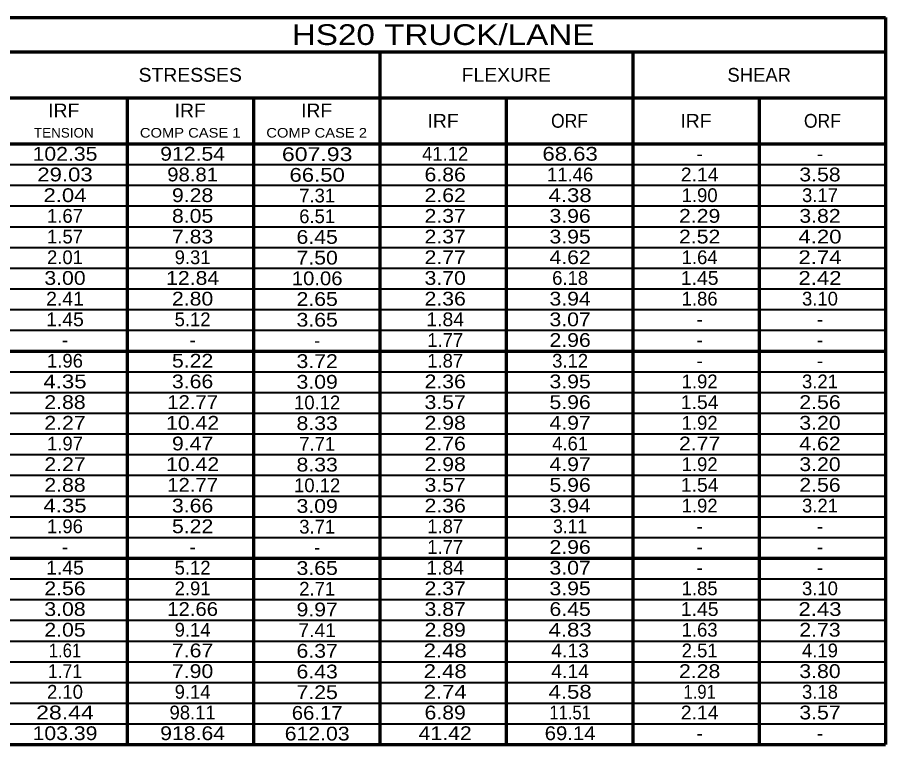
# Model space of a CAD drawing. Extents: x -1807 to -1668, y -81 to 6.
# Drawn here: x -1713.57 to -1675.8, y -25.85 to 5.78 of the extents above; entities that cross this region are included whole.
import ezdxf
from ezdxf.enums import TextEntityAlignment as Align

# ---------------------------------------------------------------- set-up
doc = ezdxf.new("R2010")
doc.units = 0
doc.header["$LTSCALE"] = 0.24
doc.layers.add('1', color=7, linetype='Continuous', lineweight=70)
doc.layers.add('5', color=7, linetype='Continuous', lineweight=40)
doc.layers.add('21', color=7, linetype='Continuous')
doc.layers.add('9', color=7, linetype='Continuous')

msp = doc.modelspace()

# ---------------------------------------------------------------- linework, layer by layer
at = {"layer": '1'}
for p, q in [((-1761.797, 5.7798), (-1675.797, 5.7798)), ((-1675.797, 5.7798), (-1675.797, -25.8503)), ((-1761.797, 4.2798), (-1675.797, 4.2798)), ((-1697.797, 4.2798), (-1697.797, -25.8503)), ((-1686.797, 4.2798), (-1686.797, -25.8503)), ((-1752.797, 2.2798), (-1675.797, 2.2798)), ((-1708.797, 2.2798), (-1708.797, -25.8503)), ((-1703.297, 2.2798), (-1703.297, -25.8503)), ((-1692.297, 2.2798), (-1692.297, -25.8503)), ((-1681.297, 2.2798), (-1681.297, -25.8503)), ((-1761.797, 0.2798), (-1675.797, 0.2798)), ((-1761.797, -8.7306), (-1675.797, -8.7306)), ((-1761.797, -17.741), (-1675.797, -17.741)), ((-1761.797, -25.8503), (-1675.797, -25.8503))]:
    msp.add_line(p, q, dxfattribs=at)
at = {"layer": '5'}
for p, q in [((-1757.797, -0.6212), (-1675.797, -0.6212)), ((-1757.797, -1.5222), (-1675.797, -1.5222)), ((-1757.797, -2.4232), (-1675.797, -2.4232)), ((-1757.797, -3.3243), (-1675.797, -3.3243)), ((-1757.797, -4.2253), (-1675.797, -4.2253)), ((-1757.797, -5.1264), (-1675.797, -5.1264)), ((-1757.797, -6.0274), (-1675.797, -6.0274)), ((-1757.797, -6.9285), (-1675.797, -6.9285)), ((-1757.797, -7.8295), (-1675.797, -7.8295)), ((-1757.797, -9.6316), (-1675.797, -9.6316)), ((-1757.797, -10.5327), (-1675.797, -10.5327)), ((-1757.797, -11.4337), (-1675.797, -11.4337)), ((-1757.797, -12.3347), (-1675.797, -12.3347)), ((-1757.797, -13.2357), (-1675.797, -13.2357)), ((-1757.797, -14.1368), (-1675.797, -14.1368)), ((-1757.797, -15.0378), (-1675.797, -15.0378)), ((-1757.797, -15.9389), (-1675.797, -15.9389)), ((-1757.797, -16.8399), (-1675.797, -16.8399)), ((-1757.797, -18.642), (-1675.797, -18.642)), ((-1757.797, -19.5431), (-1675.797, -19.5431)), ((-1757.797, -20.4441), (-1675.797, -20.4441)), ((-1757.797, -21.3452), (-1675.797, -21.3452)), ((-1757.797, -22.2462), (-1675.797, -22.2462)), ((-1757.797, -23.1472), (-1675.797, -23.1472)), ((-1757.797, -24.0482), (-1675.797, -24.0482)), ((-1757.797, -24.9493), (-1675.797, -24.9493))]:
    msp.add_line(p, q, dxfattribs=at)

# ---------------------------------------------------------------- texts
at = {"layer": '21'}
for s, height, width, p in [('STRESSES', 0.6, 1.05, (-1706.0468, 2.9798)), ('FLEXURE', 0.6, 1.05, (-1692.2968, 2.9798)), ('IRF', 0.6, 1.05, (-1711.5468, 1.4298)), ('IRF', 0.6, 1.05, (-1706.0468, 1.4298)), ('IRF', 0.6, 1.05, (-1700.5468, 1.4298)), ('IRF', 0.6, 1.05, (-1695.0468, 0.9798)), ('ORF', 0.6, 0.95, (-1689.5469, 0.9798)), ('IRF', 0.6, 1.05, (-1684.0468, 0.9798)), ('ORF', 0.6, 0.95, (-1678.5469, 0.9798)), ('TENSION', 0.4167, 1.05, (-1711.5468, 0.5525)), ('COMP CASE 1', 0.4167, 1.15, (-1706.0469, 0.5525)), ('COMP CASE 2', 0.4167, 1.15, (-1700.5469, 0.5525))]:
    msp.add_text(s, height=height, dxfattribs=dict(at, width=width)).set_placement(p, align=Align.CENTER)
msp.add_text('SHEAR', height=0.6, dxfattribs=at).set_placement((-1681.2968, 2.9798), align=Align.CENTER)
at = {"layer": '9'}
for s, height, width, p in [('HS20 TRUCK/LANE', 0.9, 1.2, (-1695.0465, 4.5798)), ('102.35', 0.6, 1.15, (-1711.4943, -0.4538)), ('912.54', 0.6, 1.15, (-1705.9427, -0.4538)), ('607.93', 0.6, 1.25, (-1700.5249, -0.4705)), ('68.63', 0.6, 1.2, (-1689.522, -0.4538)), ('29.03', 0.6, 1.2, (-1711.4944, -1.3538)), ('98.81', 0.6, 1.1, (-1705.9428, -1.3538)), ('6.86', 0.6, 1.15, (-1694.9565, -1.3538)), ('2.14', 0.6, 1.05, (-1683.8867, -1.3538)), ('3.58', 0.6, 1.15, (-1678.6528, -1.3538)), ('66.50', 0.6, 1.2, (-1700.5249, -1.3705)), ('2.04', 0.6, 1.2, (-1711.4944, -2.2538)), ('9.28', 0.6, 1.15, (-1705.9428, -2.2538)), ('2.62', 0.6, 1.15, (-1694.9565, -2.2538)), ('4.38', 0.6, 1.2, (-1689.522, -2.2538)), ('8.05', 0.6, 1.15, (-1705.9428, -3.1538)), ('2.37', 0.6, 1.15, (-1694.9565, -3.1538)), ('3.96', 0.6, 1.15, (-1689.522, -3.1538)), ('2.29', 0.6, 1.15, (-1683.8867, -3.1538)), ('3.82', 0.6, 1.15, (-1678.6528, -3.1538)), ('7.83', 0.6, 1.15, (-1705.9428, -4.0538)), ('6.45', 0.6, 1.15, (-1700.5249, -4.0705)), ('2.37', 0.6, 1.15, (-1694.9565, -4.0538)), ('3.95', 0.6, 1.15, (-1689.522, -4.0538)), ('2.52', 0.6, 1.15, (-1683.8867, -4.0538)), ('4.20', 0.6, 1.2, (-1678.6528, -4.0538)), ('7.50', 0.6, 1.15, (-1700.5249, -4.9705)), ('2.77', 0.6, 1.15, (-1694.9565, -4.9538)), ('4.62', 0.6, 1.15, (-1689.5219, -4.9538)), ('2.74', 0.6, 1.2, (-1678.6528, -4.9538)), ('3.00', 0.6, 1.15, (-1711.4943, -5.8538)), ('12.84', 0.6, 1.15, (-1705.9428, -5.8538)), ('10.06', 0.6, 1.1, (-1700.5249, -5.8705)), ('3.70', 0.6, 1.15, (-1694.9565, -5.8538)), ('1.45', 0.6, 1.05, (-1683.8867, -5.8538)), ('2.42', 0.6, 1.2, (-1678.6528, -5.8538)), ('2.41', 0.6, 1.05, (-1711.4944, -6.7538)), ('2.80', 0.6, 1.15, (-1705.9428, -6.7538)), ('2.65', 0.6, 1.15, (-1700.5249, -6.7705)), ('2.36', 0.6, 1.15, (-1694.9566, -6.7538)), ('3.94', 0.6, 1.15, (-1689.5219, -6.7538)), ('1.45', 0.6, 1.05, (-1711.4944, -7.6538)), ('3.65', 0.6, 1.15, (-1700.5249, -7.6705)), ('1.84', 0.6, 1.05, (-1694.9565, -7.6538)), ('3.07', 0.6, 1.15, (-1689.5219, -7.6538)), ('2.96', 0.6, 1.15, (-1689.522, -8.5538)), ('5.22', 0.6, 1.15, (-1705.9428, -9.4538)), ('3.72', 0.6, 1.15, (-1700.5249, -9.4705)), ('4.35', 0.6, 1.2, (-1711.4944, -10.3538)), ('3.66', 0.6, 1.15, (-1705.9428, -10.3538)), ('3.09', 0.6, 1.15, (-1700.5249, -10.3705)), ('2.36', 0.6, 1.15, (-1694.9566, -10.3538)), ('3.95', 0.6, 1.15, (-1689.522, -10.3538)), ('2.88', 0.6, 1.15, (-1711.4944, -11.2538)), ('12.77', 0.6, 1.1, (-1705.9428, -11.2538)), ('3.57', 0.6, 1.15, (-1694.9565, -11.2538)), ('5.96', 0.6, 1.15, (-1689.522, -11.2538)), ('1.54', 0.6, 1.05, (-1683.8867, -11.2538)), ('2.56', 0.6, 1.15, (-1678.6528, -11.2538)), ('2.27', 0.6, 1.15, (-1711.4944, -12.1538)), ('10.42', 0.6, 1.15, (-1705.9428, -12.1538)), ('8.33', 0.6, 1.15, (-1700.5249, -12.1705)), ('2.98', 0.6, 1.15, (-1694.9565, -12.1538)), ('4.97', 0.6, 1.15, (-1689.5219, -12.1538)), ('3.20', 0.6, 1.15, (-1678.6528, -12.1538)), ('9.47', 0.6, 1.15, (-1705.9428, -13.0538)), ('2.76', 0.6, 1.15, (-1694.9565, -13.0538)), ('2.77', 0.6, 1.15, (-1683.8867, -13.0538)), ('4.62', 0.6, 1.15, (-1678.6528, -13.0538)), ('2.27', 0.6, 1.15, (-1711.4944, -13.9538)), ('10.42', 0.6, 1.15, (-1705.9428, -13.9538)), ('8.33', 0.6, 1.15, (-1700.5249, -13.9705)), ('2.98', 0.6, 1.15, (-1694.9565, -13.9538)), ('4.97', 0.6, 1.15, (-1689.5219, -13.9538)), ('3.20', 0.6, 1.15, (-1678.6528, -13.9538)), ('2.88', 0.6, 1.15, (-1711.4944, -14.8538)), ('12.77', 0.6, 1.1, (-1705.9428, -14.8538)), ('3.57', 0.6, 1.15, (-1694.9565, -14.8538)), ('5.96', 0.6, 1.15, (-1689.522, -14.8538)), ('1.54', 0.6, 1.05, (-1683.8867, -14.8538)), ('2.56', 0.6, 1.15, (-1678.6528, -14.8538)), ('4.35', 0.6, 1.2, (-1711.4944, -15.7538)), ('3.66', 0.6, 1.15, (-1705.9428, -15.7538)), ('3.09', 0.6, 1.15, (-1700.5249, -15.7705)), ('2.36', 0.6, 1.15, (-1694.9566, -15.7538)), ('3.94', 0.6, 1.15, (-1689.5219, -15.7538)), ('5.22', 0.6, 1.15, (-1705.9428, -16.6538)), ('3.11', 0.6, 0.95, (-1689.522, -16.6538)), ('2.96', 0.6, 1.15, (-1689.522, -17.5538)), ('1.45', 0.6, 1.05, (-1711.4944, -18.4538)), ('3.65', 0.6, 1.15, (-1700.5249, -18.4705)), ('1.84', 0.6, 1.05, (-1694.9565, -18.4538)), ('3.07', 0.6, 1.15, (-1689.5219, -18.4538)), ('2.56', 0.6, 1.15, (-1711.4944, -19.3538)), ('2.37', 0.6, 1.15, (-1694.9565, -19.3538)), ('3.95', 0.6, 1.15, (-1689.522, -19.3538)), ('3.08', 0.6, 1.15, (-1711.4944, -20.2538)), ('12.66', 0.6, 1.1, (-1705.9428, -20.2538)), ('9.97', 0.6, 1.15, (-1700.5249, -20.2705)), ('3.87', 0.6, 1.15, (-1694.9565, -20.2538)), ('6.45', 0.6, 1.15, (-1689.5219, -20.2538)), ('1.45', 0.6, 1.05, (-1683.8867, -20.2538)), ('2.43', 0.6, 1.2, (-1678.6528, -20.2538)), ('2.05', 0.6, 1.15, (-1711.4944, -21.1538)), ('7.41', 0.6, 1.05, (-1700.5249, -21.1705)), ('2.89', 0.6, 1.15, (-1694.9566, -21.1538)), ('4.83', 0.6, 1.2, (-1689.522, -21.1538)), ('2.73', 0.6, 1.15, (-1678.6528, -21.1538)), ('1.61', 0.6, 0.9, (-1711.4944, -22.0538)), ('7.67', 0.6, 1.15, (-1705.9428, -22.0538)), ('6.37', 0.6, 1.15, (-1700.5249, -22.0705)), ('2.48', 0.6, 1.2, (-1694.9565, -22.0538)), ('4.13', 0.6, 1.05, (-1689.522, -22.0538)), ('1.71', 0.6, 0.95, (-1711.4943, -22.9538)), ('7.90', 0.6, 1.15, (-1705.9428, -22.9538)), ('6.43', 0.6, 1.15, (-1700.5249, -22.9705)), ('2.48', 0.6, 1.2, (-1694.9565, -22.9538)), ('4.14', 0.6, 1.05, (-1689.522, -22.9538)), ('2.28', 0.6, 1.15, (-1683.8867, -22.9538)), ('3.80', 0.6, 1.15, (-1678.6528, -22.9538)), ('7.25', 0.6, 1.15, (-1700.5249, -23.8705)), ('2.74', 0.6, 1.2, (-1694.9565, -23.8538)), ('4.58', 0.6, 1.2, (-1689.522, -23.8538)), ('1.91', 0.6, 0.9, (-1683.8867, -23.8538)), ('28.44', 0.6, 1.25, (-1711.4944, -24.7538)), ('66.17', 0.6, 1.1, (-1700.5249, -24.7705)), ('6.89', 0.6, 1.15, (-1694.9565, -24.7538)), ('11.51', 0.6, 0.9, (-1689.5219, -24.7538)), ('2.14', 0.6, 1.05, (-1683.8867, -24.7538)), ('3.57', 0.6, 1.15, (-1678.6528, -24.7538)), ('103.39', 0.6, 1.15, (-1711.4943, -25.6538)), ('918.64', 0.6, 1.15, (-1705.9428, -25.6538)), ('612.03', 0.6, 1.15, (-1700.5249, -25.6705)), ('41.42', 0.6, 1.15, (-1694.9565, -25.6538)), ('69.14', 0.6, 1.1, (-1689.522, -25.6538))]:
    msp.add_text(s, height=height, dxfattribs=dict(at, width=width)).set_placement(p, align=Align.CENTER)
for s, p in [('41.12', (-1694.9565, -0.4538)), ('-', (-1683.8867, -0.4538)), ('-', (-1678.6528, -0.4538)), ('11.46', (-1689.522, -1.3538)), ('7.31', (-1700.5249, -2.2705)), ('1.90', (-1683.8867, -2.2538)), ('3.17', (-1678.6528, -2.2538)), ('1.67', (-1711.4943, -3.1538)), ('6.51', (-1700.5248, -3.1705)), ('1.57', (-1711.4944, -4.0538)), ('2.01', (-1711.4943, -4.9538)), ('9.31', (-1705.9428, -4.9538)), ('1.64', (-1683.8867, -4.9538)), ('6.18', (-1689.5219, -5.8538)), ('1.86', (-1683.8867, -6.7538)), ('3.10', (-1678.6527, -6.7538)), ('5.12', (-1705.9428, -7.6538)), ('-', (-1683.8867, -7.6538)), ('-', (-1678.6528, -7.6538)), ('-', (-1711.4944, -8.5538)), ('-', (-1705.9428, -8.5538)), ('-', (-1700.5249, -8.5705)), ('1.77', (-1694.9565, -8.5538)), ('-', (-1683.8867, -8.5538)), ('-', (-1678.6528, -8.5538)), ('1.96', (-1711.4943, -9.4538)), ('1.87', (-1694.9565, -9.4538)), ('3.12', (-1689.522, -9.4538)), ('-', (-1683.8867, -9.4538)), ('-', (-1678.6528, -9.4538)), ('1.92', (-1683.8867, -10.3538)), ('3.21', (-1678.6528, -10.3538)), ('10.12', (-1700.5249, -11.2705)), ('1.92', (-1683.8867, -12.1538)), ('1.97', (-1711.4943, -13.0538)), ('4.61', (-1689.5219, -13.0538)), ('7.71', (-1700.5249, -13.0705)), ('1.92', (-1683.8867, -13.9538)), ('10.12', (-1700.5249, -14.8705)), ('1.92', (-1683.8867, -15.7538)), ('3.21', (-1678.6528, -15.7538)), ('1.96', (-1711.4943, -16.6538)), ('3.71', (-1700.5249, -16.6705)), ('1.87', (-1694.9565, -16.6538)), ('-', (-1683.8867, -16.6538)), ('-', (-1678.6528, -16.6538)), ('1.77', (-1694.9565, -17.5538)), ('-', (-1711.4944, -17.5538)), ('-', (-1705.9428, -17.5538)), ('-', (-1700.5249, -17.5705)), ('-', (-1683.8867, -17.5538)), ('-', (-1678.6528, -17.5538)), ('5.12', (-1705.9428, -18.4538)), ('-', (-1683.8867, -18.4538)), ('-', (-1678.6528, -18.4538)), ('2.91', (-1705.9428, -19.3538)), ('2.71', (-1700.5249, -19.3705)), ('1.85', (-1683.8867, -19.3538)), ('3.10', (-1678.6527, -19.3538)), ('9.14', (-1705.9427, -21.1538)), ('1.63', (-1683.8867, -21.1538)), ('2.51', (-1683.8867, -22.0538)), ('4.19', (-1678.6528, -22.0538)), ('2.10', (-1711.4943, -23.8538)), ('9.14', (-1705.9427, -23.8538)), ('3.18', (-1678.6528, -23.8538)), ('98.11', (-1705.9428, -24.7538)), ('-', (-1683.8867, -25.6538)), ('-', (-1678.6528, -25.6538))]:
    msp.add_text(s, height=0.6, dxfattribs=at).set_placement(p, align=Align.CENTER)

doc.saveas('drawing.dxf')
